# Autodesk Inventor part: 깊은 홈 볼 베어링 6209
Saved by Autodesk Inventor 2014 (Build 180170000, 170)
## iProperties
Created: 2025-06
Part Number: 깊은 홈 볼 베어링 6209
Material: 일반
Document SubType Name: Modeling
Designer: dg
Density: 1 g/cm^3
Appearance: 기본값
Author: dg
Author: jhkim
Description: 깊은 그루부 볼 베어링
Creation Date: 2025-05-23
Sending System: Autodesk Inventor 2026
Preprocessor: ST-DEVELOPER v20.1
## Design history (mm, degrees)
node "깊은 홈 볼 베어링 62091"
body "Solid1"
node "Solid1_1"
node "Solid1_2"
node "Solid1_3"
node "Solid1_4"
node "Solid1_5"
node "Solid1_6"
node "Solid1_7"
node "Solid1_8"
node "Solid1_9"
node "Solid1_10"
node "Solid1_11"
node "기준1"
node "기준2"
node "기준3"
node "기준4"
node "기준5"
node "기준6"
node "기준7"
node "기준8"
node "기준9"
node "기준10"
node "기준11"
node "기준12"
